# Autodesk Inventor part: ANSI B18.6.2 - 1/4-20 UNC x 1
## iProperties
Comments: To add or edit properties for Autodesk Inventor files, use iProperties.
Created: 2004-12
Part Number: ANSI B18.6.2 - 1/4-20 UNC x 1
Vendor: Autodesk Inc.
Document SubType Name: Modeling
Designer: John Blackburn
Material: Default
Description: Slotted Flat Countersunk Head Cap Screw
Standard: ANSI B18.6.2
Alert: To add or edit properties for Autodesk Inventor files, use iProperties.
Control State: 0
Master: False
Checked Out: False
Shininess: 64.0
Length Units: 11272
Angle Units: 11279
Time Units: 11290
Mass Units: 11286
Length Display Precision: 3
Angle Display Precision: 2
Compacted: True
EGR: 3
Classification: un/spsc 31161513
Density: 0.0
Volumn: 0.0
Area: 0.0
PropertySet Name: Model Information
Author: John Blackburn
Revision Number: 8
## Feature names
1. Body [Revolution]
2. Slot [Extrusion]
3. Chamfer1
